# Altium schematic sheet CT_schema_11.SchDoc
size 741 x 377 mm
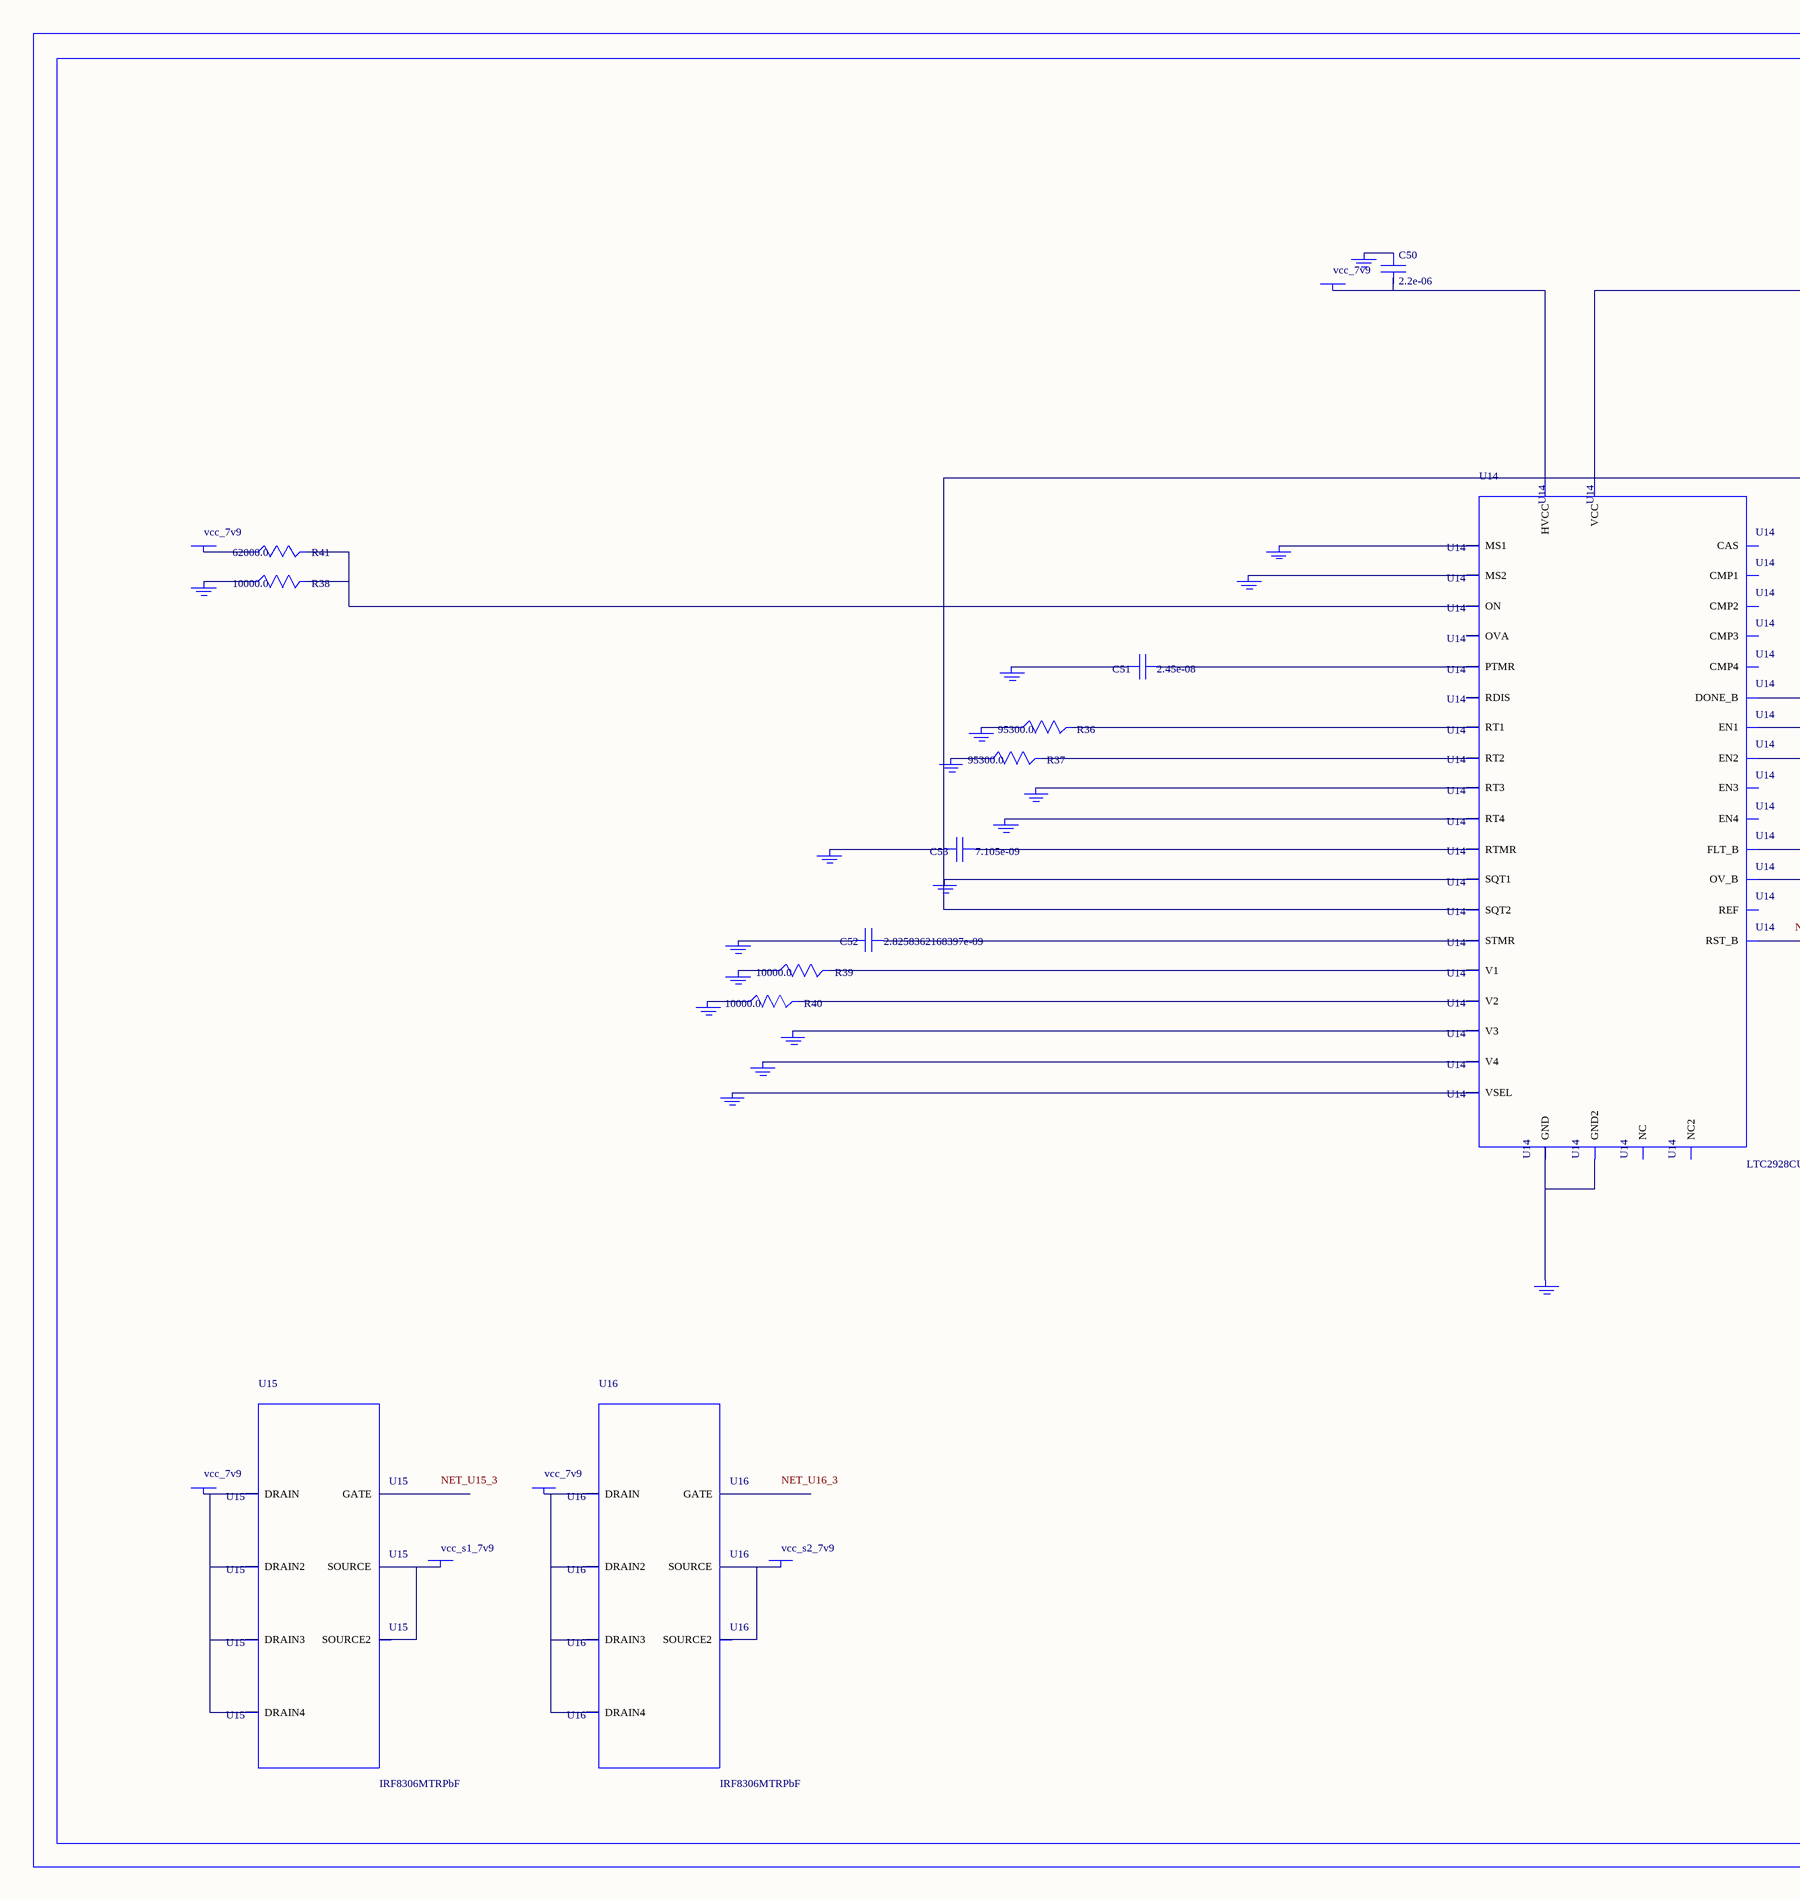
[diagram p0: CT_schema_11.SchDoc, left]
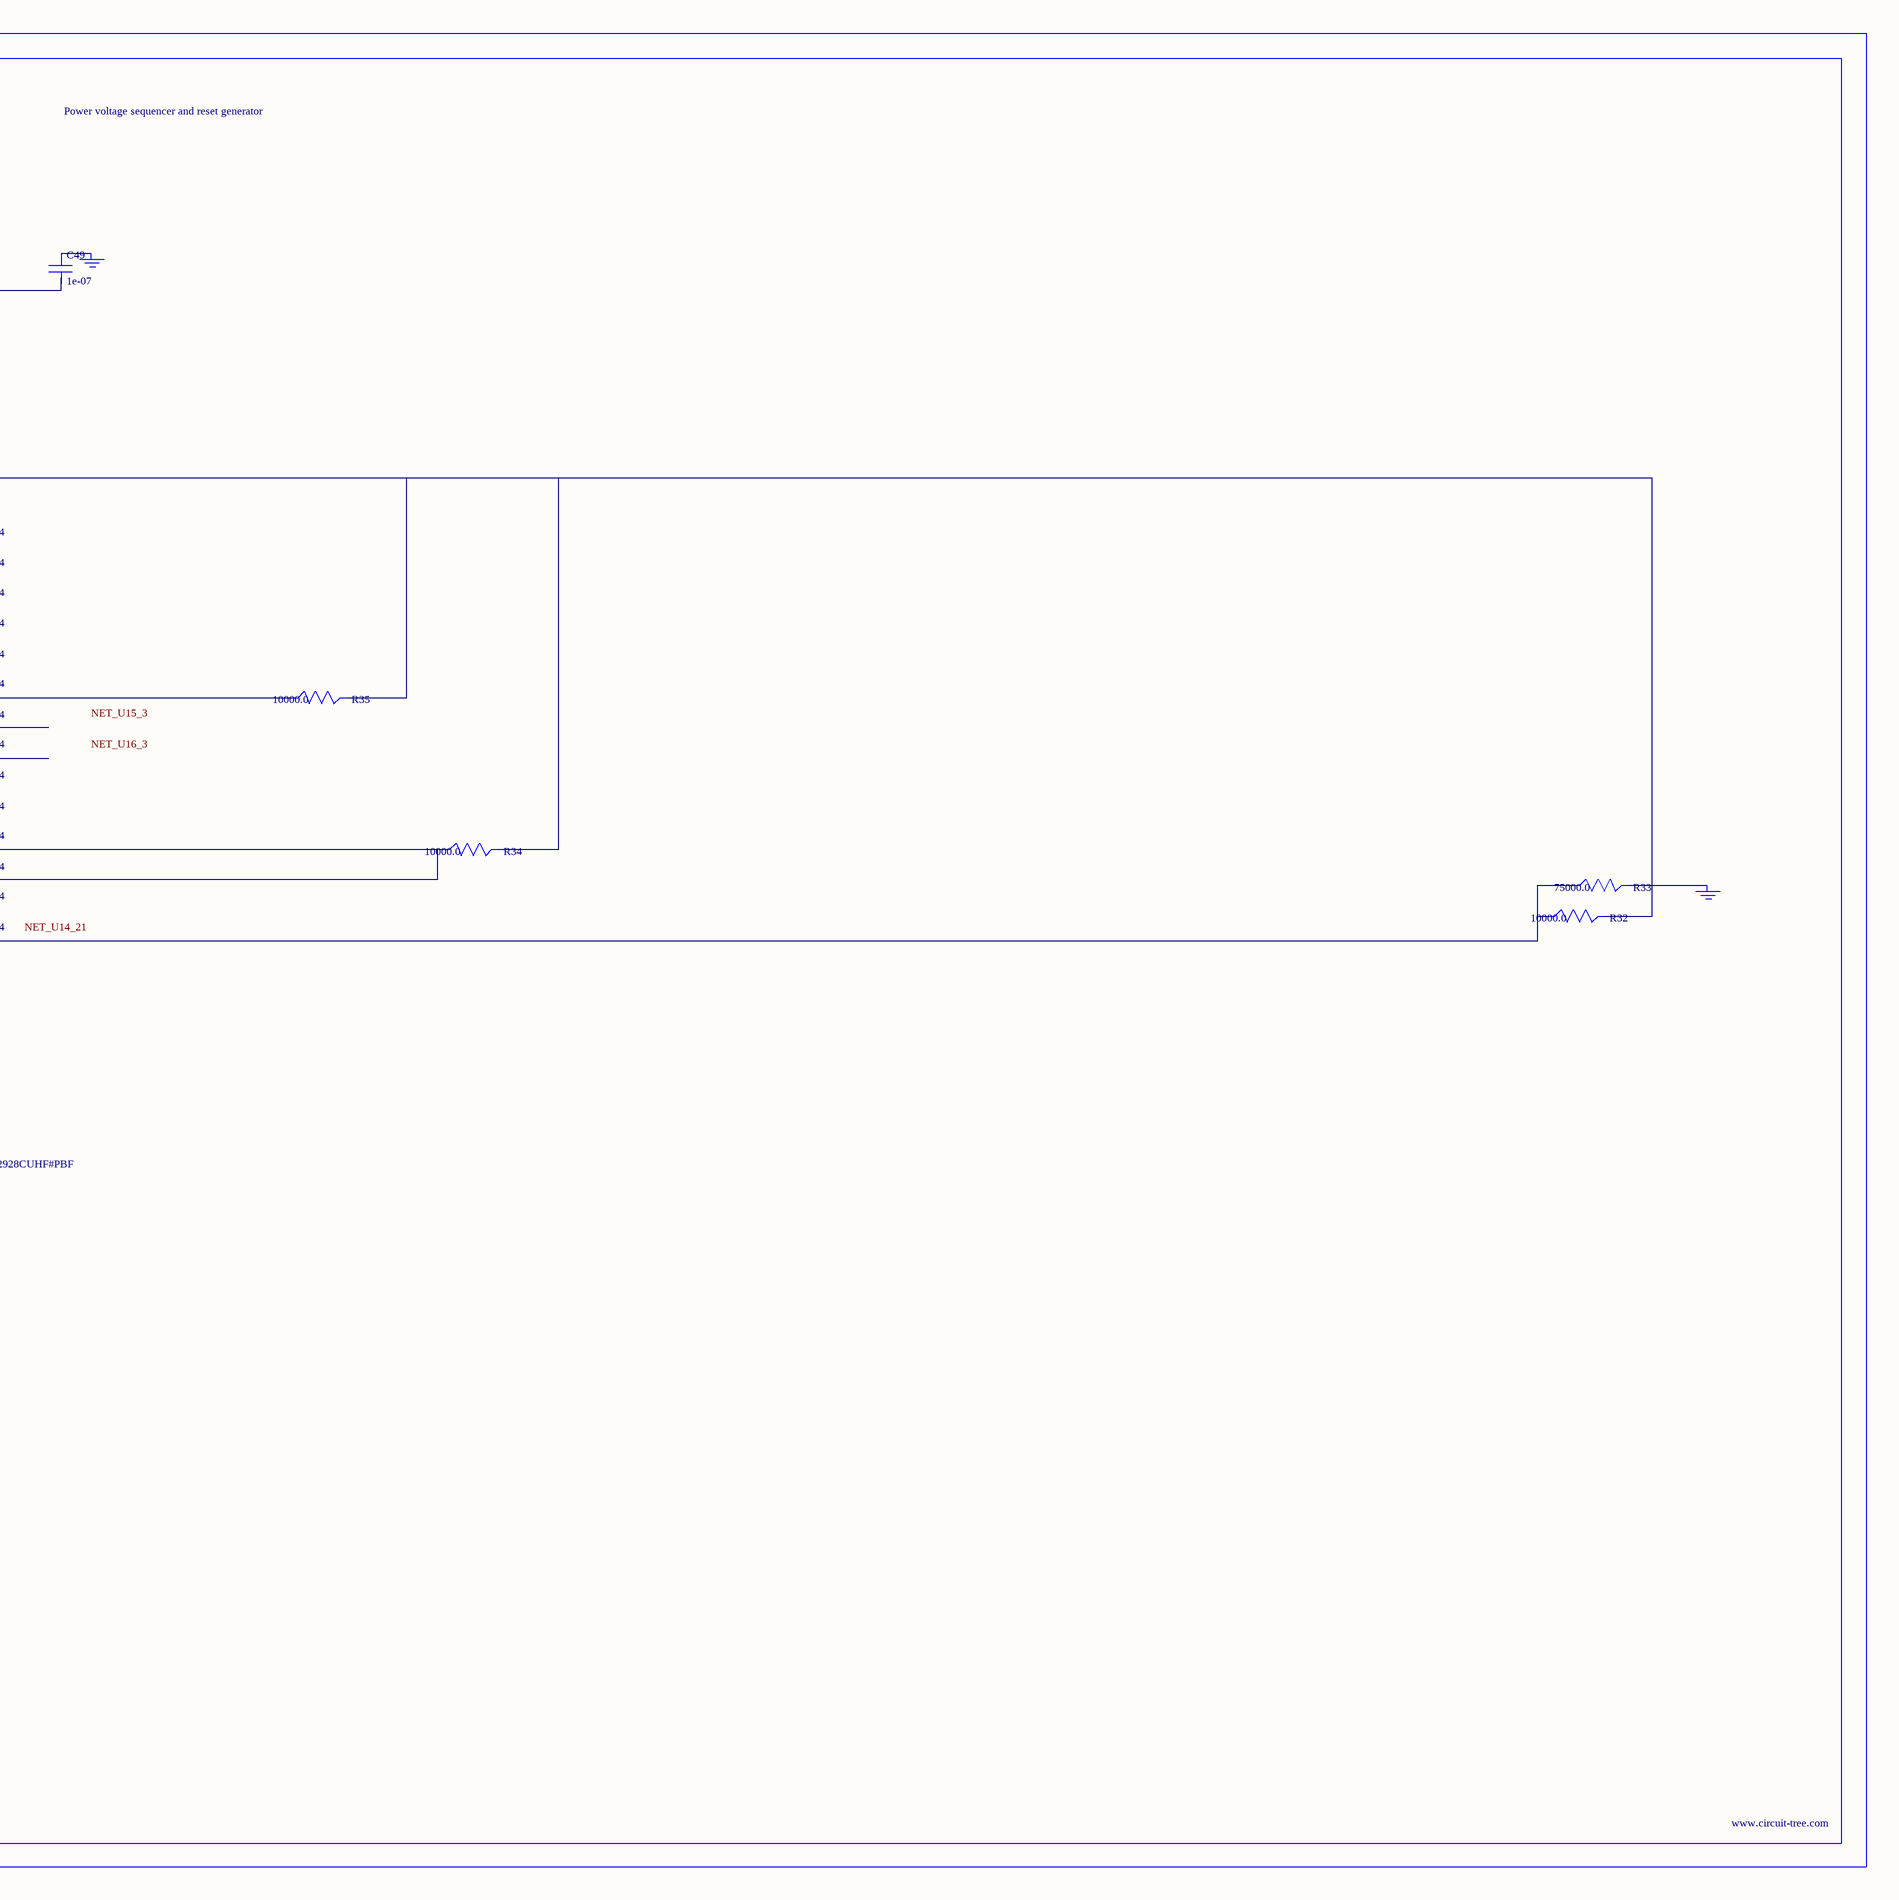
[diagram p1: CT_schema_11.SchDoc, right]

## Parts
BORDER10  (no value)
C49  1e-07  [C0402]
C50  2.2e-06  [C0603]
C51  2.45e-08  [R0603]
C52  2.8258362168397e-09  [R0603]
C53  7.105e-09  [R0603]
GND_INSTANCE_10_0  (no value)
GND_INSTANCE_10_1  (no value)
GND_INSTANCE_10_2  (no value)
GND_INSTANCE_10_3  (no value)
GND_INSTANCE_10_4  (no value)
GND_INSTANCE_10_5  (no value)
GND_INSTANCE_10_6  (no value)
GND_INSTANCE_10_7  (no value)
GND_INSTANCE_10_8  (no value)
GND_INSTANCE_10_9  (no value)
GND_INSTANCE_10_10  (no value)
GND_INSTANCE_10_11  (no value)
GND_INSTANCE_10_12  (no value)
GND_INSTANCE_10_13  (no value)
GND_INSTANCE_10_14  (no value)
GND_INSTANCE_10_15  (no value)
GND_INSTANCE_10_16  (no value)
GND_INSTANCE_10_17  (no value)
GND_INSTANCE_10_18  (no value)
GND_INSTANCE_10_19  (no value)
POWER_INSTANCE_10_0  vcc_7v9
POWER_INSTANCE_10_1  vcc_7v9
POWER_INSTANCE_10_2  vcc_7v9
POWER_INSTANCE_10_3  vcc_s1_7v9
POWER_INSTANCE_10_4  vcc_7v9
POWER_INSTANCE_10_5  vcc_s2_7v9
R32  10000.0  [R0603]
R33  75000.0  [R0603]
R34  10000.0  [R0603]
R35  10000.0  [R0603]
R36  95300.0  [R0603]
R37  95300.0  [R0603]
R38  10000.0  [R0603]
R39  10000.0  [R0603]
R40  10000.0  [R0603]
R41  62000.0  [R0603]
U14  LTC2928CUHF#PBF  [QFN-38_UHF]
U15  IRF8306MTRPbF  [IRF8306MTRPBF]
U16  IRF8306MTRPbF  [IRF8306MTRPBF]

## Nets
NetC49_1: C49.1 GND_INSTANCE_10_10.0(GND)
NetC49_2: C49.2 C53.2 GND_INSTANCE_10_5.0(GND) GND_INSTANCE_10_15.0(GND) R32.2 R34.2 R35.2 U14.10(SQT1) U14.11(SQT2) U14.22(VCC)
NetC50_1: C50.1 GND_INSTANCE_10_11.0(GND)
NetC50_2: C50.2 POWER_INSTANCE_10_1.0(PWR) U14.23(HVCC)
NetC51_1: C51.1 U14.27(PTMR)
NetC51_2: C51.2 GND_INSTANCE_10_14.0(GND)
NetC52_1: C52.1 U14.26(STMR)
NetC52_2: C52.2 GND_INSTANCE_10_13.0(GND)
NetC53_1: C53.1 U14.28(RTMR)
NetGND_INSTANCE_10_0_0: GND_INSTANCE_10_0.0(GND) R39.1
NetGND_INSTANCE_10_1_0: GND_INSTANCE_10_1.0(GND) R36.1
NetGND_INSTANCE_10_2_0: GND_INSTANCE_10_2.0(GND) R37.1
NetGND_INSTANCE_10_3_0: GND_INSTANCE_10_3.0(GND) U14.8(RT3)
NetGND_INSTANCE_10_4_0: GND_INSTANCE_10_4.0(GND) U14.9(RT4)
NetGND_INSTANCE_10_6_0: GND_INSTANCE_10_6.0(GND) U14.12(MS1)
NetGND_INSTANCE_10_7_0: GND_INSTANCE_10_7.0(GND) U14.13(MS2)
NetGND_INSTANCE_10_8_0: GND_INSTANCE_10_8.0(GND) R38.1
NetGND_INSTANCE_10_9_0: GND_INSTANCE_10_9.0(GND) R33.2
NetGND_INSTANCE_10_12_0: GND_INSTANCE_10_12.0(GND) U14.25(VSEL)
NetGND_INSTANCE_10_16_0: GND_INSTANCE_10_16.0(GND) U14.30(V4)
NetGND_INSTANCE_10_17_0: GND_INSTANCE_10_17.0(GND) U14.32(V3)
NetGND_INSTANCE_10_18_0: GND_INSTANCE_10_18.0(GND) R40.1
NetGND_INSTANCE_10_19_0: GND_INSTANCE_10_19.0(GND) U14.24(GND) U14.39(GND2)
NetPOWER_INSTANCE_10_0_0: POWER_INSTANCE_10_0.0(PWR) R41.1
NetPOWER_INSTANCE_10_2_0: POWER_INSTANCE_10_2.0(PWR) U15.1(DRAIN) U15.2(DRAIN2) U15.6(DRAIN3) U15.7(DRAIN4)
NetPOWER_INSTANCE_10_3_0: POWER_INSTANCE_10_3.0(PWR) U15.4(SOURCE) U15.5(SOURCE2)
NetPOWER_INSTANCE_10_4_0: POWER_INSTANCE_10_4.0(PWR) U16.1(DRAIN) U16.2(DRAIN2) U16.6(DRAIN3) U16.7(DRAIN4)
NetPOWER_INSTANCE_10_5_0: POWER_INSTANCE_10_5.0(PWR) U16.4(SOURCE) U16.5(SOURCE2)
NetR32_1: R32.1 R33.1 U14.21(RST_B)
NetR34_1: R34.1 U14.19(FLT_B) U14.20(OV_B)
NetR35_1: R35.1 U14.18(DONE_B)
NetR36_2: R36.2 U14.6(RT1)
NetR37_2: R37.2 U14.7(RT2)
NetR38_2: R38.2 R41.2 U14.16(ON)
NetR39_2: R39.2 U14.3(V1)
NetR40_2: R40.2 U14.38(V2)

Not connected (* = marked no-connect by the designer): U14 1(OVA) 2(EN1) 4(NC) 5(REF) 14(RDIS) 15(CAS) 17(NC2) 29(EN4) 31(EN3) 33(CMP3) 34(CMP4) 35(CMP1) 36(CMP2) 37(EN2); U15 3(GATE); U16 3(GATE)

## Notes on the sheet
- Labels drawn without touching a wire or pin: NET_U14_21, NET_U15_3, NET_U16_3

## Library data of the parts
BORDER10 = BORDER_PAGE10
C49 = C0402C104K3RACTU
C50 = GRM188R61H225KE1115D
C51 = C51
C52 = C52
C53 = C53
GND_INSTANCE_10_0-GND_INSTANCE_10_19 = GND
POWER_INSTANCE_10_0-POWER_INSTANCE_10_5 = PWR
R32 R34 R35 R38-R40 = RC0603JR-0710KL
R33 = RC0603JR-0775KL
R36 R37 = RC0603FR-0795K3L
R41 = RC0603JR-0762KL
